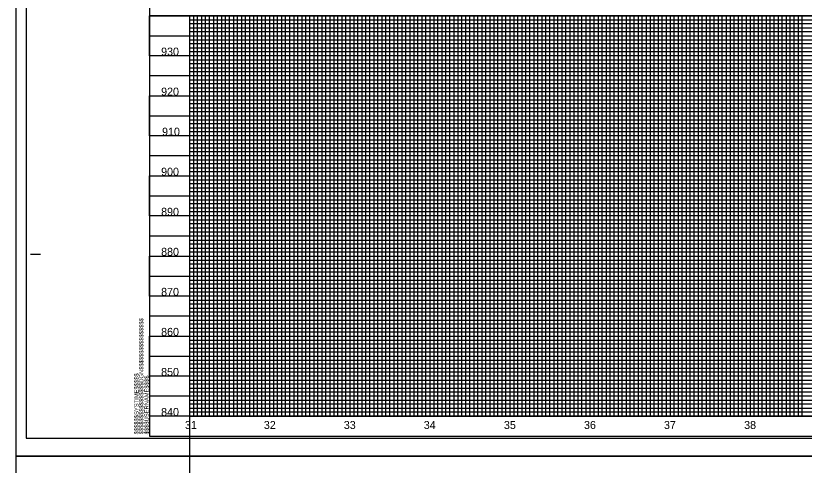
# Model space of a CAD drawing. Extents: x 1967929 to 1975641, y 546296 to 568534.
# Drawn here: x 1969864 to 1970849, y 567423 to 567984 of the extents above; entities that cross this region are included whole.
import ezdxf

# ---------------------------------------------------------------- set-up
doc = ezdxf.new("R2010")
doc.units = 0
for name, color, linetype in [('Exist Vertical Profile Horizontal Axis Label Major', 7, 'Continuous'), ('Exist Vertical Profile Vertical Axis Label', 7, 'Continuous'), ('Old_Level_41', 7, 'Continuous'), ('Old_Level_42', 7, 'Continuous'), ('Scratch_Level_3', 7, 'Continuous'), ('Sheet Cutting Line CELL', 7, 'Continuous'), ('Sheet Plot Border Inside CELL', 7, 'Continuous'), ('Sheet Plot Border Outside CELL', 7, 'Continuous'), ('Sheet Profile CELL', 7, 'Continuous'), ('Sheet Profile Grid Major CELL', 7, 'Continuous'), ('Sheet Profile Grid Middle CELL', 7, 'Continuous'), ('Sheet Profile Grid Minor CELL', 7, 'Continuous')]:
    doc.layers.add(name, color=color, linetype=linetype)

msp = doc.modelspace()

# ---------------------------------------------------------------- linework, layer by layer
at = {"layer": 'Old_Level_41'}
msp.add_line((1969882.95, 567686.36), (1969895.45, 567686.36), dxfattribs=at)
at = {"layer": 'Old_Level_42'}
msp.add_line((1970031.45, 567483.86), (1970031.45, 567483.86), dxfattribs=at)
at = {"layer": 'Scratch_Level_3'}
for points in [[(1970081.45, 567983.86), (1970081.45, 567483.86), (1971481.45, 567483.86), (1971481.45, 567983.86)], [(1970081.45, 567983.86), (1970081.45, 567483.86), (1971381.45, 567483.86), (1971381.45, 567983.86)], [(1970081.45, 567983.86), (1970081.45, 567483.86), (1971481.45, 567483.86), (1971481.45, 567983.86)], [(1970081.45, 567983.86), (1970081.45, 567483.86), (1971481.45, 567483.86), (1971481.45, 567752.23), (1971481.45, 567983.86), (1971331.4, 567983.86)], [(1970081.45, 567508.86), (1970081.45, 567008.86), (1971481.45, 567008.86), (1971481.5, 567312.53), (1971331.45, 567312.51), (1971331.4, 567508.86)]]:
    msp.add_lwpolyline(points, close=True, dxfattribs=at)
at = {"layer": 'Sheet Cutting Line CELL'}
for p, q in [((1969864.45, 568533.86), (1969864.45, 567433.86)), ((1969864.45, 567433.86), (1971548.45, 567433.86)), ((1969864.45, 567433.86), (1969864.45, 566333.86))]:
    msp.add_line(p, q, dxfattribs=at)
at = {"layer": 'Sheet Plot Border Inside CELL'}
msp.add_lwpolyline([(1969877.45, 567456.31), (1971543.95, 567456.31), (1971543.95, 568511.41), (1969877.45, 568511.41)], close=True, dxfattribs=at)
at = {"layer": 'Sheet Plot Border Outside CELL'}
for points in [[(1969864.45, 567433.86), (1971548.45, 567433.86), (1971548.45, 568533.86), (1969864.45, 568533.86)], [(1969864.45, 566333.86), (1971548.45, 566333.86), (1971548.45, 567433.86), (1969864.45, 567433.86)]]:
    msp.add_lwpolyline(points, close=True, dxfattribs=at)
at = {"layer": 'Sheet Profile CELL'}
for p, q in [((1971531.45, 567983.86), (1970031.45, 567983.86)), ((1971531.45, 567483.86), (1970031.45, 567483.86))]:
    msp.add_line(p, q, dxfattribs=at)
msp.add_lwpolyline([(1971531.45, 568508.86), (1970031.45, 568508.86), (1970031.45, 567458.86), (1971531.45, 567458.86)], close=True, dxfattribs=at)
at = {"layer": 'Sheet Profile Grid Major CELL'}
for points in [[(1971531.45, 567933.86), (1970031.45, 567933.86), (1970031.45, 567983.86), (1971531.45, 567983.86)], [(1970081.45, 567983.86), (1970081.45, 567483.86), (1970131.45, 567483.86), (1970131.45, 567983.86)], [(1970181.45, 567983.86), (1970181.45, 567483.86), (1970231.45, 567483.86), (1970231.45, 567983.86)], [(1970281.45, 567983.86), (1970281.45, 567483.86), (1970331.45, 567483.86), (1970331.45, 567983.86)], [(1970381.45, 567983.86), (1970381.45, 567483.86), (1970431.45, 567483.86), (1970431.45, 567983.86)], [(1970481.45, 567983.86), (1970481.45, 567483.86), (1970531.45, 567483.86), (1970531.45, 567983.86)], [(1970581.45, 567983.86), (1970581.45, 567483.86), (1970631.45, 567483.86), (1970631.45, 567983.86)], [(1970681.45, 567983.86), (1970681.45, 567483.86), (1970731.45, 567483.86), (1970731.45, 567983.86)], [(1970781.45, 567983.86), (1970781.45, 567483.86), (1970831.45, 567483.86), (1970831.45, 567983.86)], [(1971531.45, 567833.86), (1970031.45, 567833.86), (1970031.45, 567883.86), (1971531.45, 567883.86)], [(1971531.45, 567733.86), (1970031.45, 567733.86), (1970031.45, 567783.86), (1971531.45, 567783.86)], [(1971531.45, 567633.86), (1970031.45, 567633.86), (1970031.45, 567683.86), (1971531.45, 567683.86)], [(1971531.45, 567533.86), (1970031.45, 567533.86), (1970031.45, 567583.86), (1971531.45, 567583.86)]]:
    msp.add_lwpolyline(points, dxfattribs=at)
at = {"layer": 'Sheet Profile Grid Middle CELL'}
for points in [[(1970031.45, 567983.86), (1970031.45, 567958.86), (1971531.45, 567958.86)], [(1970106.45, 567483.86), (1970106.45, 567983.86)], [(1970156.45, 567983.86), (1970156.45, 567483.86), (1970206.45, 567483.86), (1970206.45, 567983.86)], [(1970256.45, 567983.86), (1970256.45, 567483.86), (1970306.45, 567483.86), (1970306.45, 567983.86)], [(1970356.45, 567983.86), (1970356.45, 567483.86), (1970406.45, 567483.86), (1970406.45, 567983.86)], [(1970456.45, 567983.86), (1970456.45, 567483.86), (1970506.45, 567483.86), (1970506.45, 567983.86)], [(1970556.45, 567983.86), (1970556.45, 567483.86), (1970606.45, 567483.86), (1970606.45, 567983.86)], [(1970656.45, 567983.86), (1970656.45, 567483.86), (1970706.45, 567483.86), (1970706.45, 567983.86)], [(1970756.45, 567983.86), (1970756.45, 567483.86), (1970806.45, 567483.86), (1970806.45, 567983.86)], [(1971531.45, 567908.86), (1970031.45, 567908.86), (1970031.45, 567858.86), (1971531.45, 567858.86)], [(1971531.45, 567808.86), (1970031.45, 567808.86), (1970031.45, 567758.86), (1971531.45, 567758.86)], [(1971531.45, 567708.86), (1970031.45, 567708.86), (1970031.45, 567658.86), (1971531.45, 567658.86)], [(1971531.45, 567608.86), (1970031.45, 567608.86), (1970031.45, 567558.86), (1971531.45, 567558.86)], [(1971531.45, 567508.86), (1970031.45, 567508.86)]]:
    msp.add_lwpolyline(points, dxfattribs=at)
at = {"layer": 'Sheet Profile Grid Minor CELL'}
for points in [[(1970081.45, 567978.86), (1971481.45, 567978.86)], [(1970086.45, 567983.86), (1970086.45, 567483.86), (1970091.45, 567483.86), (1970091.45, 567983.86)], [(1970096.45, 567983.86), (1970096.45, 567483.86), (1970101.45, 567483.86), (1970101.45, 567983.86)], [(1970111.45, 567983.86), (1970111.45, 567483.86), (1970116.45, 567483.86), (1970116.45, 567983.86)], [(1970121.45, 567983.86), (1970121.45, 567483.86), (1970126.45, 567483.86), (1970126.45, 567983.86)], [(1970136.45, 567983.86), (1970136.45, 567483.86), (1970141.45, 567483.86), (1970141.45, 567983.86)], [(1970146.45, 567983.86), (1970146.45, 567483.86), (1970151.45, 567483.86), (1970151.45, 567983.86)], [(1970161.45, 567983.86), (1970161.45, 567483.86), (1970166.45, 567483.86), (1970166.45, 567983.86)], [(1970171.45, 567983.86), (1970171.45, 567483.86), (1970176.45, 567483.86), (1970176.45, 567983.86)], [(1970186.45, 567983.86), (1970186.45, 567483.86), (1970191.45, 567483.86), (1970191.45, 567983.86)], [(1970196.45, 567983.86), (1970196.45, 567483.86), (1970201.45, 567483.86), (1970201.45, 567983.86)], [(1970211.45, 567983.86), (1970211.45, 567483.86), (1970216.45, 567483.86), (1970216.45, 567983.86)], [(1970221.45, 567983.86), (1970221.45, 567483.86), (1970226.45, 567483.86), (1970226.45, 567983.86)], [(1970236.45, 567983.86), (1970236.45, 567483.86), (1970241.45, 567483.86), (1970241.45, 567983.86)], [(1970246.45, 567483.86), (1970251.45, 567483.86), (1970251.45, 567983.86)], [(1970246.45, 567983.86), (1970246.45, 567483.86)], [(1970261.45, 567983.86), (1970261.45, 567483.86), (1970266.45, 567483.86), (1970266.45, 567983.86)], [(1970271.45, 567983.86), (1970271.45, 567483.86), (1970276.45, 567483.86), (1970276.45, 567983.86)], [(1970286.45, 567983.86), (1970286.45, 567483.86), (1970291.45, 567483.86), (1970291.45, 567983.86)], [(1970296.45, 567983.86), (1970296.45, 567483.86), (1970301.45, 567483.86), (1970301.45, 567983.86)], [(1970311.45, 567983.86), (1970311.45, 567483.86), (1970316.45, 567483.86), (1970316.45, 567983.86)], [(1970321.45, 567983.86), (1970321.45, 567483.86), (1970326.45, 567483.86), (1970326.45, 567983.86)], [(1970336.45, 567983.86), (1970336.45, 567483.86), (1970341.45, 567483.86), (1970341.45, 567983.86)], [(1970346.45, 567983.86), (1970346.45, 567483.86), (1970351.45, 567483.86), (1970351.45, 567983.86)], [(1970361.45, 567983.86), (1970361.45, 567483.86), (1970366.45, 567483.86), (1970366.45, 567983.86)], [(1970371.45, 567983.86), (1970371.45, 567483.86), (1970376.45, 567483.86), (1970376.45, 567983.86)], [(1970386.45, 567983.86), (1970386.45, 567483.86), (1970391.45, 567483.86), (1970391.45, 567983.86)], [(1970396.45, 567983.86), (1970396.45, 567483.86), (1970401.45, 567483.86), (1970401.45, 567983.86)], [(1970411.45, 567983.86), (1970411.45, 567483.86), (1970426.45, 567483.86), (1970426.45, 567983.86)], [(1970416.45, 567983.86), (1970416.45, 567483.86), (1970421.45, 567483.86), (1970421.45, 567983.86)], [(1970436.45, 567983.86), (1970436.45, 567483.86), (1970441.45, 567483.86), (1970441.45, 567983.86)], [(1970446.45, 567983.86), (1970446.45, 567483.86), (1970451.45, 567483.86), (1970451.45, 567983.86)], [(1970461.45, 567983.86), (1970461.45, 567483.86), (1970466.45, 567483.86), (1970466.45, 567983.86)], [(1970471.45, 567983.86), (1970471.45, 567483.86), (1970476.45, 567483.86), (1970476.45, 567983.86)], [(1970486.45, 567983.86), (1970486.45, 567483.86), (1970491.45, 567483.86), (1970491.45, 567983.86)], [(1970496.45, 567983.86), (1970496.45, 567483.86), (1970501.45, 567483.86), (1970501.45, 567983.86)], [(1970511.45, 567983.86), (1970511.45, 567483.86), (1970516.45, 567483.86), (1970516.45, 567983.86)], [(1970521.45, 567983.86), (1970521.45, 567483.86), (1970526.45, 567483.86), (1970526.45, 567983.86)], [(1970536.45, 567983.86), (1970536.45, 567483.86), (1970541.45, 567483.86), (1970541.45, 567983.86)], [(1970546.45, 567983.86), (1970546.45, 567483.86), (1970551.45, 567483.86), (1970551.45, 567983.86)], [(1970561.45, 567983.86), (1970561.45, 567483.86)], [(1970566.45, 567983.86), (1970566.45, 567483.86), (1970571.45, 567483.86), (1970571.45, 567983.86)], [(1970576.45, 567983.86), (1970576.45, 567483.86), (1970586.45, 567483.86), (1970586.45, 567983.86)], [(1970591.45, 567983.86), (1970591.45, 567483.86), (1970596.45, 567483.86), (1970596.45, 567983.86)], [(1970601.45, 567983.86), (1970601.45, 567483.86)], [(1970611.45, 567483.86), (1970611.45, 567983.86)], [(1970616.45, 567983.86), (1970616.45, 567483.86), (1970621.45, 567483.86), (1970621.45, 567983.86)], [(1970626.45, 567983.86), (1970626.45, 567483.86), (1970636.45, 567483.86), (1970636.45, 567983.86)], [(1970641.45, 567983.86), (1970641.45, 567483.86), (1970641.45, 567483.86), (1970646.45, 567483.86), (1970646.45, 567983.86)], [(1970651.45, 567983.86), (1970651.45, 567483.86), (1970661.45, 567483.86), (1970661.45, 567983.86)], [(1970666.45, 567983.86), (1970666.45, 567483.86), (1970671.45, 567483.86), (1970671.45, 567983.86)], [(1970676.45, 567983.86), (1970676.45, 567483.86), (1970686.45, 567483.86), (1970686.45, 567983.86)], [(1970691.45, 567983.86), (1970691.45, 567483.86), (1970696.45, 567483.86), (1970696.45, 567983.86)], [(1970701.45, 567983.86), (1970701.45, 567483.86), (1970711.45, 567483.86), (1970711.45, 567983.86)], [(1970716.45, 567983.86), (1970716.45, 567483.86), (1970721.45, 567483.86), (1970721.45, 567983.86)], [(1970726.45, 567983.86), (1970726.45, 567483.86), (1970736.45, 567483.86), (1970736.45, 567983.86)], [(1970741.45, 567983.86), (1970741.45, 567483.86), (1970746.45, 567483.86), (1970746.45, 567983.86)], [(1970751.45, 567983.86), (1970751.45, 567483.86), (1970761.45, 567483.86), (1970761.45, 567983.86)], [(1970766.45, 567983.86), (1970766.45, 567483.86), (1970771.45, 567483.86), (1970771.45, 567983.86)], [(1970776.45, 567983.86), (1970776.45, 567483.86), (1970786.45, 567483.86), (1970786.45, 567983.86)], [(1970791.45, 567983.86), (1970791.45, 567483.86)], [(1970791.45, 567483.86), (1970796.45, 567483.86), (1970796.45, 567983.86)], [(1970801.45, 567983.86), (1970801.45, 567483.86), (1970811.45, 567483.86), (1970811.45, 567983.86)], [(1970816.45, 567983.86), (1970816.45, 567483.86), (1970821.45, 567483.86), (1970821.45, 567983.86)], [(1970826.45, 567983.86), (1970826.45, 567483.86), (1970836.45, 567483.86), (1970836.45, 567983.86)], [(1970841.45, 567983.86), (1970841.45, 567483.86), (1970846.45, 567483.86), (1970846.45, 567983.86)], [(1971481.45, 567973.86), (1970081.45, 567973.86), (1970081.45, 567968.86), (1971481.45, 567968.86)], [(1971481.45, 567963.86), (1970081.45, 567963.86), (1970081.45, 567953.86), (1971481.45, 567953.86)], [(1971481.45, 567948.86), (1970081.45, 567948.86), (1970081.45, 567943.86), (1971481.45, 567943.86)], [(1971481.45, 567938.86), (1970081.45, 567938.86), (1970081.45, 567928.86), (1971481.45, 567928.86)], [(1971481.45, 567923.86), (1970081.45, 567923.86), (1970081.45, 567918.86), (1971481.45, 567918.86)], [(1971481.45, 567913.86), (1970081.45, 567913.86), (1970081.45, 567903.86), (1971481.45, 567903.86)], [(1971481.45, 567898.86), (1970081.45, 567898.86), (1970081.45, 567893.86), (1971481.45, 567893.86)], [(1971481.45, 567888.86), (1970081.45, 567888.86), (1970081.45, 567878.86), (1971481.45, 567878.86)], [(1971481.45, 567873.86), (1970081.45, 567873.86), (1970081.45, 567868.86), (1971481.45, 567868.86)], [(1971481.45, 567863.86), (1970081.45, 567863.86), (1970081.45, 567853.86), (1971481.45, 567853.86)], [(1971481.45, 567848.86), (1970081.45, 567848.86), (1970081.45, 567843.86), (1971481.45, 567843.86)], [(1971481.45, 567838.86), (1970081.45, 567838.86), (1970081.45, 567828.86), (1971481.45, 567828.86)], [(1971481.45, 567823.86), (1970081.45, 567823.86), (1970081.45, 567818.86), (1971481.45, 567818.86)], [(1971481.45, 567813.86), (1970081.45, 567813.86), (1970081.45, 567803.86), (1971481.45, 567803.86)], [(1971481.45, 567798.86), (1970081.45, 567798.86), (1970081.45, 567793.86), (1971481.45, 567793.86)], [(1971481.45, 567788.86), (1970081.45, 567788.86), (1970081.45, 567778.86), (1971481.45, 567778.86)], [(1971481.45, 567773.86), (1970081.45, 567773.86), (1970081.45, 567768.86), (1971481.45, 567768.86)], [(1971481.45, 567763.86), (1970081.45, 567763.86), (1970081.45, 567753.86), (1971481.45, 567753.86)], [(1971481.45, 567748.86), (1970081.45, 567748.86), (1970081.45, 567743.86), (1971481.45, 567743.86)], [(1971481.45, 567738.86), (1970081.45, 567738.86), (1970081.45, 567728.86), (1971481.45, 567728.86)], [(1971481.45, 567723.86), (1970081.45, 567723.86), (1970081.45, 567718.86), (1971481.45, 567718.86)], [(1971481.45, 567713.86), (1970081.45, 567713.86), (1970081.45, 567703.86), (1971481.45, 567703.86)], [(1971481.45, 567698.86), (1970081.45, 567698.86), (1970081.45, 567693.86), (1971481.45, 567693.86)], [(1971481.45, 567688.86), (1970081.45, 567688.86)], [(1970081.45, 567678.86), (1971481.45, 567678.86)], [(1971481.45, 567673.86), (1970081.45, 567673.86), (1970081.45, 567668.86), (1971481.45, 567668.86)], [(1971481.45, 567663.86), (1970081.45, 567663.86)], [(1970081.45, 567653.86), (1971481.45, 567653.86)], [(1971481.45, 567648.86), (1970081.45, 567648.86), (1970081.45, 567643.86), (1971481.45, 567643.86)], [(1971481.45, 567638.86), (1970081.45, 567638.86), (1970081.45, 567628.86), (1971481.45, 567628.86)], [(1971481.45, 567623.86), (1970081.45, 567623.86), (1970081.45, 567618.86), (1971481.45, 567618.86)], [(1971481.45, 567613.86), (1970081.45, 567613.86), (1970081.45, 567603.86), (1971481.45, 567603.86)], [(1971481.45, 567598.86), (1970081.45, 567598.86), (1970081.45, 567593.86), (1971481.45, 567593.86)], [(1971481.45, 567588.86), (1970081.45, 567588.86), (1970081.45, 567578.86), (1971481.45, 567578.86)], [(1971481.45, 567573.86), (1970081.45, 567573.86), (1970081.45, 567568.86), (1971481.45, 567568.86)], [(1971481.45, 567563.86), (1970081.45, 567563.86), (1970081.45, 567553.86), (1971481.45, 567553.86)], [(1971481.45, 567548.86), (1970081.45, 567548.86), (1970081.45, 567543.86), (1971481.45, 567543.86)], [(1971481.45, 567538.86), (1970081.45, 567538.86), (1970081.45, 567528.86), (1971481.45, 567528.86)], [(1971481.45, 567523.86), (1970081.45, 567523.86), (1970081.45, 567518.86), (1971481.45, 567518.86)], [(1971481.45, 567513.86), (1970081.45, 567513.86), (1970081.45, 567503.86), (1971481.45, 567503.86)], [(1971481.45, 567498.86), (1970081.45, 567498.86), (1970081.45, 567493.86), (1971481.45, 567493.86)], [(1971481.45, 567488.86), (1970081.45, 567488.86), (1970081.45, 567483.86), (1971481.45, 567483.86)]]:
    msp.add_lwpolyline(points, dxfattribs=at)

# ---------------------------------------------------------------- texts
at = {"layer": 'Exist Vertical Profile Horizontal Axis Label Major'}
for s, p in [('31', (1970075.68, 567467.89)), ('32', (1970174.22, 567467.89)), ('33', (1970274.06, 567467.89)), ('34', (1970373.9, 567467.89)), ('35', (1970473.99, 567467.89)), ('36', (1970573.93, 567467.89)), ('37', (1970673.79, 567467.89)), ('38', (1970773.92, 567467.89))]:
    msp.add_text(s, height=10, dxfattribs=at).set_placement(p)
at = {"layer": 'Exist Vertical Profile Vertical Axis Label'}
for s, p in [('930', (1970045.92, 567934.11)), ('920', (1970045.92, 567884.11)), ('910', (1970047.11, 567834.11)), ('900', (1970045.92, 567784.11)), ('890', (1970045.92, 567734.11)), ('880', (1970045.92, 567684.11)), ('870', (1970045.92, 567634.11)), ('860', (1970045.92, 567584.11)), ('850', (1970045.92, 567534.11)), ('840', (1970045.92, 567484.11))]:
    msp.add_text(s, height=10, dxfattribs=at).set_placement(p)
at = {"layer": 'Sheet Profile CELL'}
for s, p in [('$$$$$$$$$$$$$$$$DGN$$$$$$$$$$$$$$$$', (1970023.8, 567461.23)), ('$$$$$$SYSTIME$$$$$', (1970017.75, 567461.23)), ('$$$$USERNAME$$$$', (1970030.37, 567461.24))]:
    msp.add_text(s, height=5.25, rotation=90, dxfattribs=at).set_placement(p)

doc.saveas('drawing.dxf')
